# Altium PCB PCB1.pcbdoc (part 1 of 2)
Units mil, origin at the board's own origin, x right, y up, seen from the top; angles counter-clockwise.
Board outline 5175 x 2060 mil, 4 copper layers (Top Layer, Inner1, Inner2, Bottom Layer), stack 62.447 mil thick; 102 components, 59 nets, 316 pads, 177 vias.
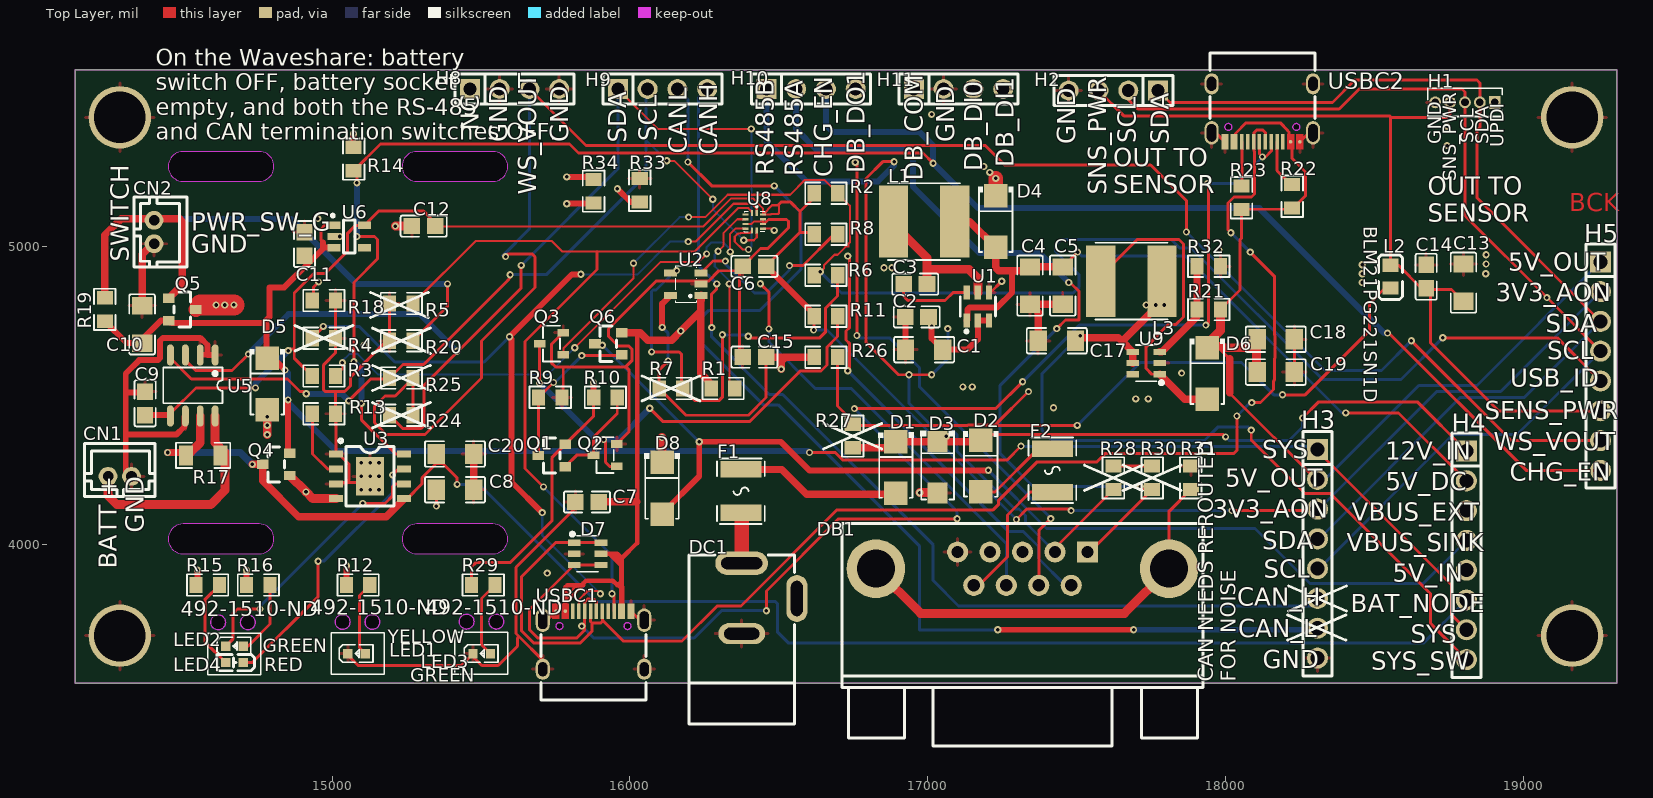
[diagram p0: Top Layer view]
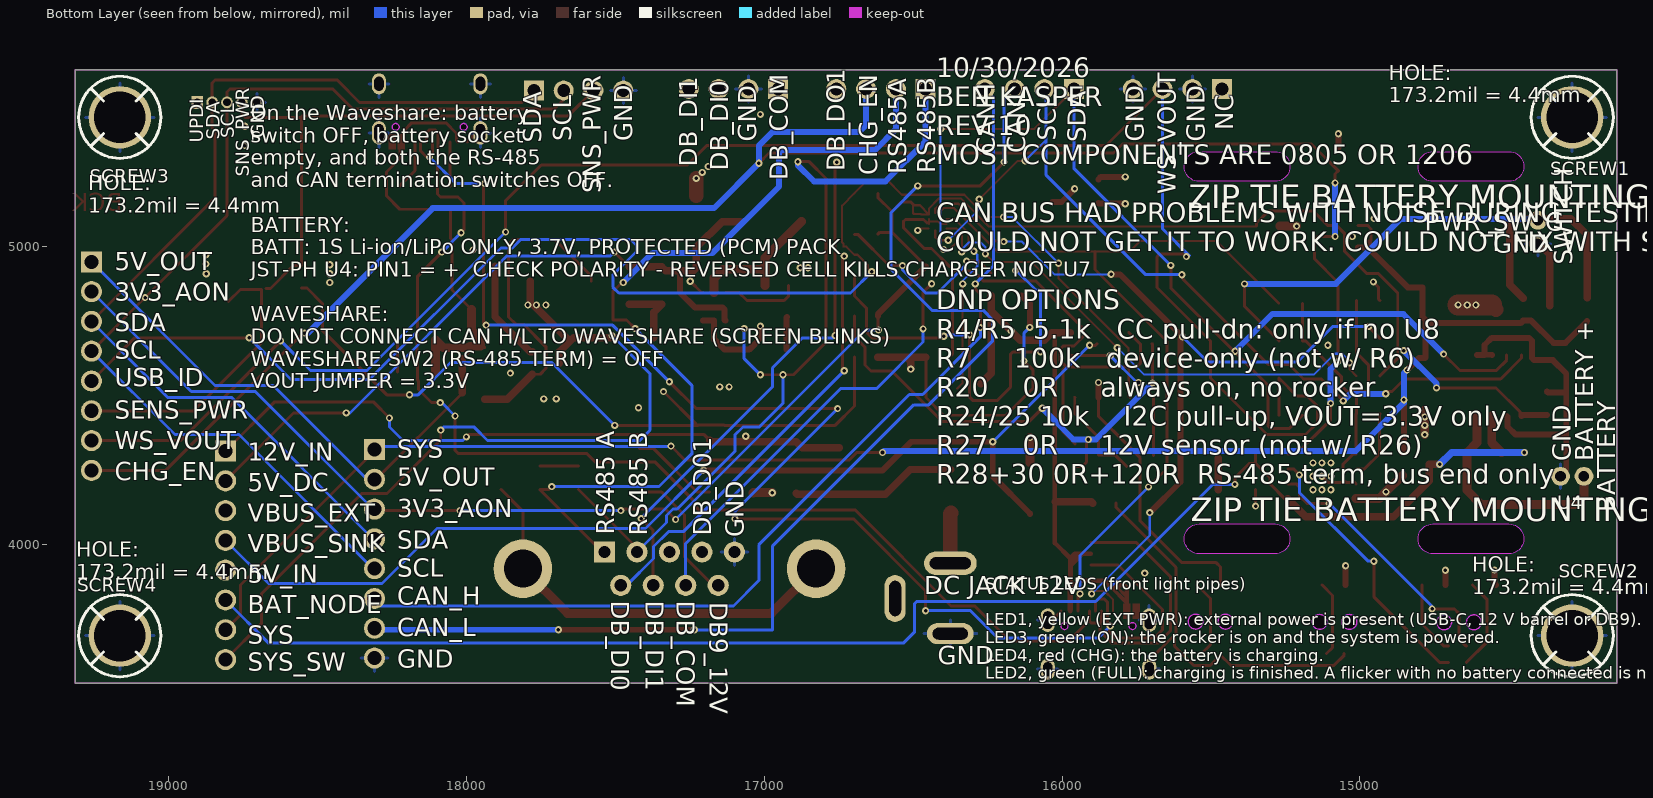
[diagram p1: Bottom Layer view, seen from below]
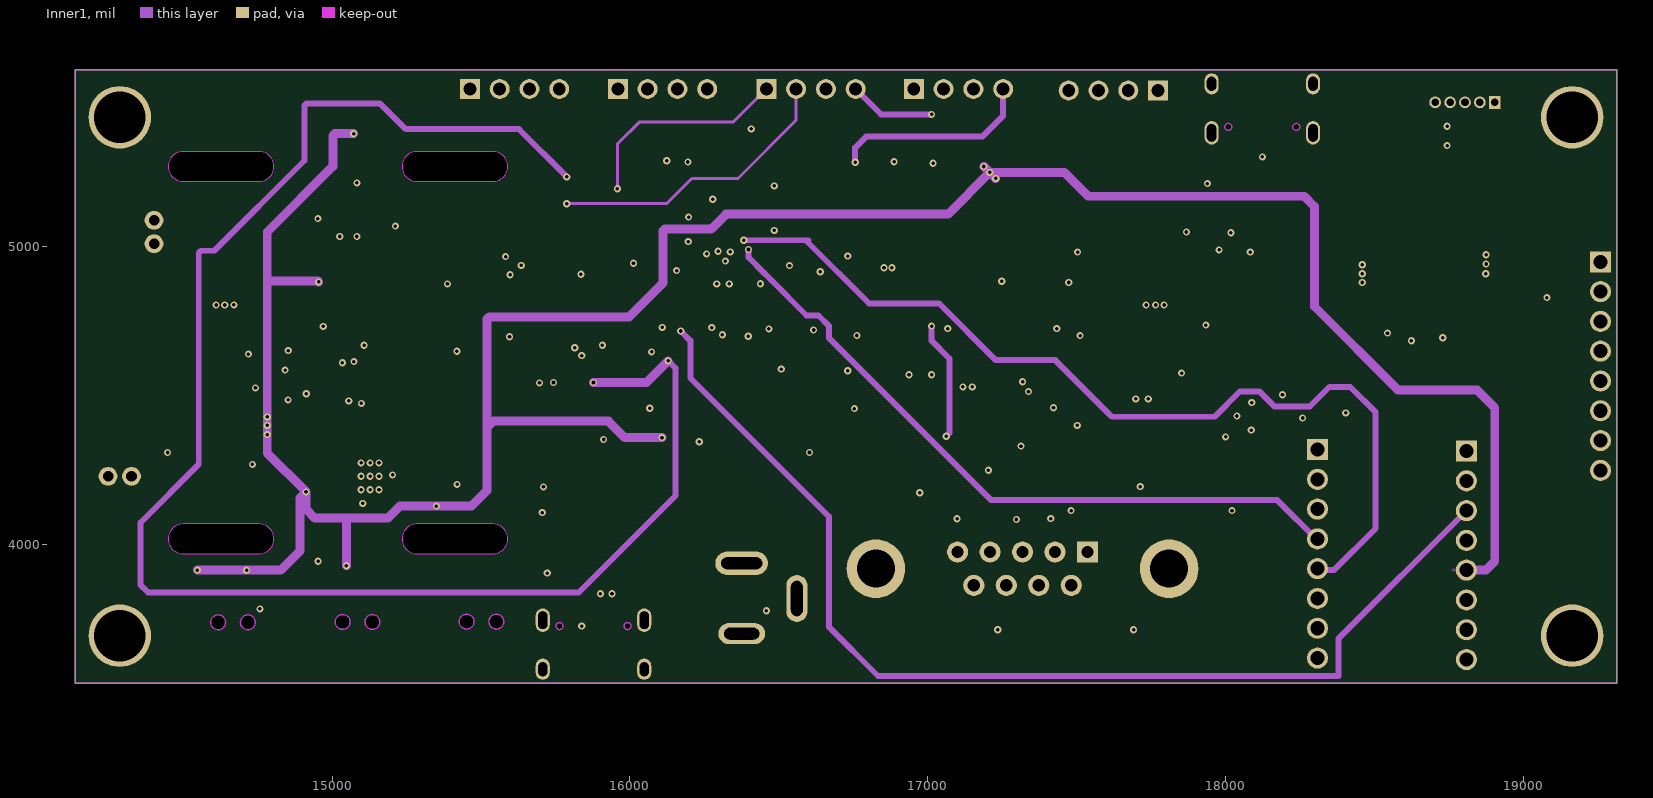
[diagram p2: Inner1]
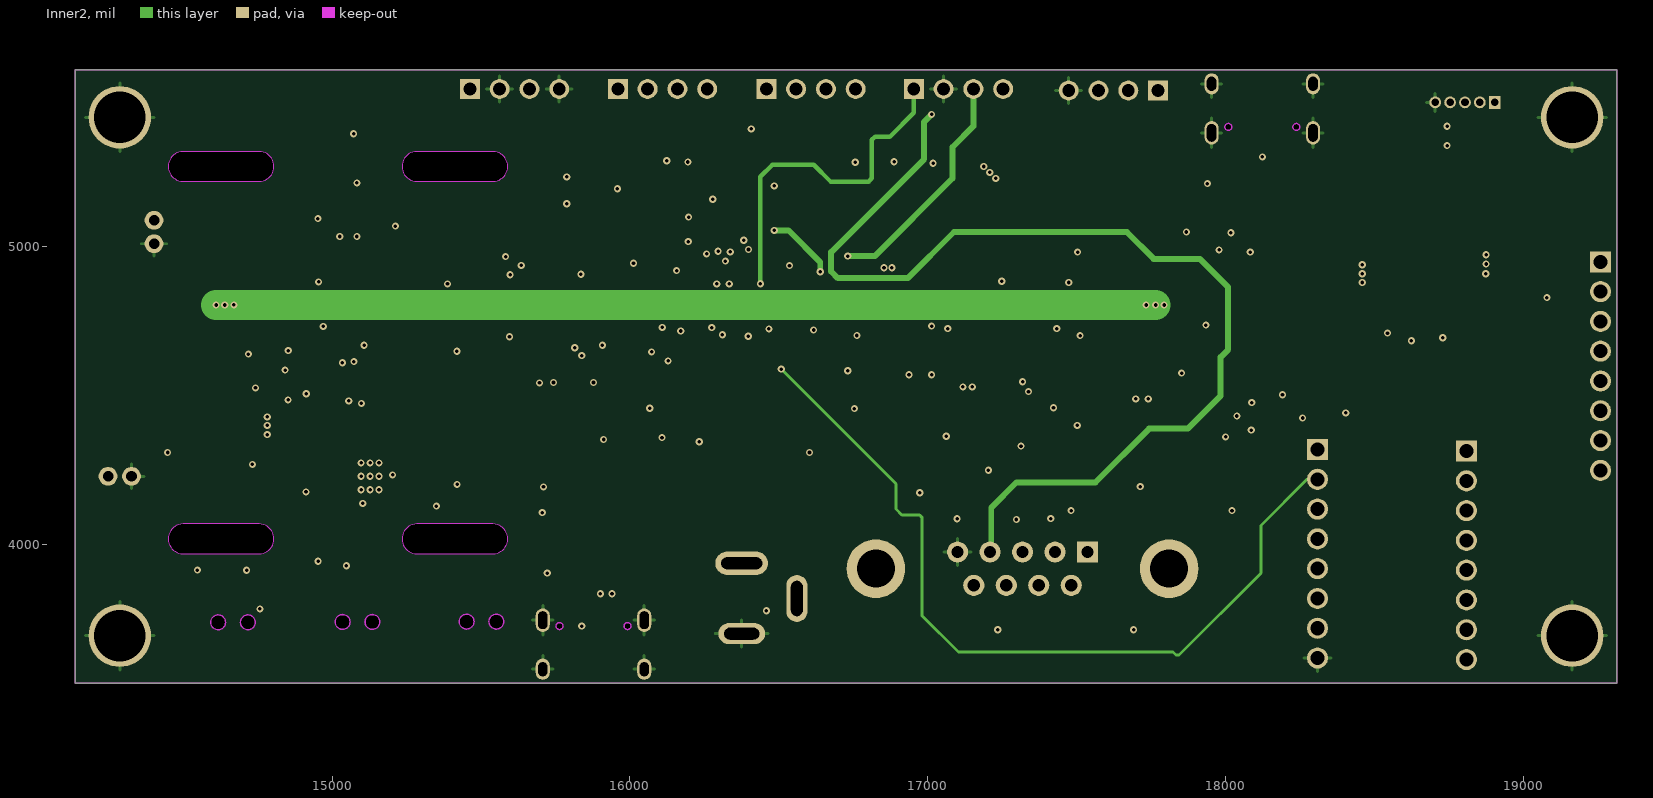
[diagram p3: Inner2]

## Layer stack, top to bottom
Top Layer: signal copper 1.378
Dielectric1: surface 8.283, 7628 RC49% 8.6mil, Dk 0
Inner1: signal copper 0.598
Dielectric2: surface 41.929, 1.1mm H/HOZ Copper, Dk 0
Inner2: signal copper 0.598
Dielectric3: surface 8.283, 7628 RC49% 8.6mil, Dk 0
Bottom Layer: signal copper 1.378

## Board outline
14137.5,5595 14137.5,3535 19312.5,3535 19312.5,5595
cut-out: 14500,5320 ccw(c14500,5270) 14450,5270 ccw(c14500,5270) 14500,5220 14755,5220 ccw(c14755,5270) 14805,5270 ccw(c14755,5270) 14755,5320
cut-out: 15285,5320 ccw(c15285,5270) 15235,5270 ccw(c15285,5270) 15285,5220 15540,5220 ccw(c15540,5270) 15590,5270 ccw(c15540,5270) 15540,5320
cut-out: 14500,4070 ccw(c14500,4020) 14450,4020 ccw(c14500,4020) 14500,3970 14755,3970 ccw(c14755,4020) 14805,4020 ccw(c14755,4020) 14755,4070
cut-out: 15285,4070 ccw(c15285,4020) 15235,4020 ccw(c15285,4020) 15285,3970 15540,3970 ccw(c15540,4020) 15590,4020 ccw(c15540,4020) 15540,4070
cut-out: 14642.5,3740 cw(c14617.5,3740) 14592.5,3740 cw(c14617.5,3740)
cut-out: 14742.5,3740 cw(c14717.5,3740) 14692.5,3740 cw(c14717.5,3740)
cut-out: 15060.5,3741.25 cw(c15035.5,3741.25) 15010.5,3741.25 cw(c15035.5,3741.25)
cut-out: 15160.5,3741.25 cw(c15135.5,3741.25) 15110.5,3741.25 cw(c15135.5,3741.25)
cut-out: 15476.5,3742.25 cw(c15451.5,3742.25) 15426.5,3742.25 cw(c15451.5,3742.25)
cut-out: 15576.5,3742.3 cw(c15551.5,3742.3) 15526.5,3742.3 cw(c15551.5,3742.3)

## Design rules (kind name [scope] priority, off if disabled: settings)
BoardOutlineClearance copperThickness1oz [All] p0: genericclearance=10 ignorepadtopadclearanceinfootprint=FALSE except(0: Arc-SplitContinuation Track-SplitContinuation SMDPad-SplitContinuation THPad-SplitContinuation Via-SplitContinuation Fill-SplitContinuation Poly-SplitContinuation Region-SplitContinuation Text-SplitContinuation)
BoardOutlineClearance copperThickness2oz [All] p0: genericclearance=10 ignorepadtopadclearanceinfootprint=FALSE except(0: Arc-SplitContinuation Track-SplitContinuation SMDPad-SplitContinuation THPad-SplitContinuation Via-SplitContinuation Fill-SplitContinuation Poly-SplitContinuation Region-SplitContinuation Text-SplitContinuation)
BoardOutlineClearance safeClearance1 [All] p0: genericclearance=10 ignorepadtopadclearanceinfootprint=FALSE except(0: Arc-SplitContinuation Track-SplitContinuation SMDPad-SplitContinuation THPad-SplitContinuation Via-SplitContinuation Fill-SplitContinuation Poly-SplitContinuation Region-SplitContinuation Text-SplitContinuation)
BoardOutlineClearance otherClearance [All] p0: genericclearance=10 ignorepadtopadclearanceinfootprint=FALSE except(0: Arc-SplitContinuation Track-SplitContinuation SMDPad-SplitContinuation THPad-SplitContinuation Via-SplitContinuation Fill-SplitContinuation Poly-SplitContinuation Region-SplitContinuation Text-SplitContinuation)
Clearance copperThickness1oz [All] p1: gap=7 ignorepadtopadclearanceinfootprint=FALSE
Clearance copperThickness2oz [All] p1: gap=7 ignorepadtopadclearanceinfootprint=FALSE
Clearance safeClearance1 [All] p1: gap=7 ignorepadtopadclearanceinfootprint=FALSE
Clearance otherClearance [All] p1: gap=7 ignorepadtopadclearanceinfootprint=FALSE
DiffPairsRouting differentialPair [All] p1: maxuncoupledlength=10 minlimit=6 maxlimit=Infinity mostfreqgap=6 toplayer_minwidth=5 toplayer_prefwidth=10 toplayer_maxwidth=100 bottomlayer_minwidth=5 bottomlayer_prefwidth=10 bottomlayer_maxwidth=100 midlayer1_minwidth=5 midlayer1_prefwidth=10 midlayer1_maxwidth=100 midlayer2_minwidth=5 midlayer2_prefwidth=10 midlayer2_maxwidth=100
PasteMaskExpansion pasteMaskExpansion [All] p1: expansion=0
PlaneConnect innerPlane [All] p1: planeconnectstyle=Relief reliefexpansion=20 reliefentries=4 reliefconductorwidth=10 reliefairgap=10
PolygonConnect copperRegion [All] p1: connectstyle=Relief reliefentries=4 reliefconductorwidth=10 polygonreliefangle="90 Angle" airgapwidth=10
RoutingVias viaSize [All] p1: viastyle="Through Hole" holewidth=12.0078 minholewidth=11.811 maxholewidth=248.0314 width=12.0078 minwidth=11.811 maxwidth=248.0314
SolderMaskExpansion solderMaskExpansion [IsVia] p1: useseparateexpansions=TRUE expansion=-1000 expansionbottom=-1000
SolderMaskExpansion solderMaskExpansion [All] p2: useseparateexpansions=TRUE expansion=2 expansionbottom=2
Width copperThickness1oz [All] p1: maxlimit=100 minlimit=5 preferedwidth=10
Width copperThickness2oz [All] p1: maxlimit=100 minlimit=8 preferedwidth=10

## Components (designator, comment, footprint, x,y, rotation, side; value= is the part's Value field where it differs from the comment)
C1 "22uF" C1206 16987.5,4655 r0 top
C2 "100nF" C0805 16962.5,4765 r0 top
C3 "100nF" C0805 16957.5,4875 r180 top
C4 "22uF" C1206 17342.5,4870 r90 top
C5 "22uF" C1206 17452.5,4870 r90 top
C6 "100nF" C0805 16417.5,4935 r0 top
C7 "1uF" C0805 15855.7,4143.7 r180 top
C8 "22uF" C1206 15412.5,4185 r180 top
C9 "100nF" C0805 14372.5,4475 r270 top
C10 "22uF" C1206 14362.5,4740 r270 top
C11 "1uF" C0805 14907.5,5010 r270 top
C12 "1uF" C0805 15307.5,5070 r0 top
C13 "22uF" C1206 18797.5,4880 r90 top
C14 "100nF" C0805 18672.5,4900 r270 top
C15 "100nF" C0805 16417.5,4630 r0 top
C17 "22uF" C1206 17432.5,4685 r180 top
C18 "22uF" C1206 18167.5,4690 r0 top
C19 "22uF" C1206 18167.5,4580 r0 top
C20 "22uF" C1206 15412.5,4305 r180 top
CN1 "B2B-PH-K-S(LF)(SN)" CONN-TH_B2B-PH-K-S 14287.5,4230 r0 top
CN2 "B2B-PH-K-S(LF)(SN)" CONN-TH_B2B-PH-K-S 14402.5,5050 r270 top
D1 "SS34" SMA_L4.3-W2.6-LS5.2-RD 16892.5,4260 r270 top
D2 "SS34" SMA_L4.3-W2.6-LS5.2-RD 17177.5,4264.23 r270 top
D3 "SMAJ18A" SMA_L4.4-W2.6-LS5.0-RD 17032.5,4260 r270 top
D4 "SS34" SMA_L4.3-W2.6-LS5.2-RD 17227.5,5085 r270 top
D5 "SS34" SMA_L4.3-W2.6-LS5.2-RD 14782.5,4540 r270 top
D6 "SS34" SMA_L4.3-W2.6-LS5.2-RD 17937.5,4575 r270 top
D7 "USBLC6-2SC6" SOT-23-6_L2.9-W1.6-P0.95-LS2.8-BL 15857.5,3970 r270 top
D8 "SS34" SMA_L4.3-W2.6-LS5.2-RD 16107.5,4190 r270 top
DB1 "A-DF 09 A/KG-T2S" DB9-TH_DB9F_C9900018961 17317.5,3920 r0 top
DC1 "PJ-002AH" DC-IN-TH_PJ-002AH 16467.5,3820 r270 top
F1 "BSMD1812-150-33V" F1812 16372.5,4180 r90 top
F2 "BSMD1812-150-33V" F1812 17417.5,4250 r90 top
H1 "GRPB051VWVN-RC" HDR-TH_5P-P1.27-V-M-1 18802.5,5485 r180 top
H2 "" HDR-TH_4P-P2.54-V-M 17622.5,5525 r180 top
H3 "" HDR-TH_8P-P2.54-V-F-1 18307.5,3970 r270 top
H4 "" HDR-TH_8P-P2.54-V-F-1 18807.5,3965 r270 top
H5 "" HDR-TH_8P-P2.54-V-F-1 19257.5,4600 r270 top
H8 "" HDR-TH_4P-P2.54-V-M 15612.5,5530 r0 top
H9 "" HDR-TH_4P-P2.54-V-M 16109.17,5530 r0 top
H10 "" HDR-TH_4P-P2.54-V-M 16607.5,5530 r0 top
H11 "" HDR-TH_4P-P2.54-V-M 17102.5,5530 r0 top
L1 "6.8uH" IND-SMD_L6.0-W6.0_SMNR6045 16987.5,5085 r180 top
L2 "BLM21PG221SN1D" L0805 18552.5,4900 r90 top
L3 "6.8uH" IND-SMD_L6.0-W6.0_SMNR6045 17682.5,4885 r0 top
LED1 "NCD0603Y2" LED0603-RD 15082.5,3635 r0 top
LED2 "KT-0603G" LED0603-RD 14672.5,3660 r0 top
LED3 "KT-0603G" LED0603-RD 15502.5,3635 r0 top
LED4 "KT-0603R" LED-SMD_L1.6-W0.8-R-RD 14672.5,3605 r180 top
Q1 "AO3401A" SOT-23_L2.9-W1.3-P1.90-LS2.4-BR 15737.5,4300 r0 top
Q2 "2N7002" SOT-23-3_L2.9-W1.3-P1.90-LS2.4-BR 15916.59,4300.97 r0 top
Q3 "2N7002" SOT-23-3_L2.9-W1.3-P1.90-LS2.4-BR 15736.59,4675 r0 top
Q4 "AO3401A" SOT-23_L2.9-W1.3-P1.90-LS2.4-BR 14812.5,4270 r0 top
Q5 "AO3401A" SOT-23_L2.9-W1.3-P1.90-LS2.4-BR 14497.5,4790 r180 top
Q6 "AO3401A" SOT-23_L2.9-W1.3-P1.90-LS2.4-BR 15927.5,4675 r0 top
R1 "910kΩ" R0805 16312.5,4525 r0 top
R2 "100kΩ" R0805 16657.5,5180 r0 top
R3 "100kΩ" R0805 14972.5,4566.67 r0 top
R4 "5.1kΩ" R0805 14972.5,4693.33 r0 top
R5 "5.1kΩ" R0805 15232.5,4810 r180 top
R6 "0Ω" R0805 16657.5,4905 r0 top
R7 "100kΩ" R0805 16137.5,4525 r0 top
R8 "10kΩ" R0805 16657.5,5042.5 r0 top
R9 "100kΩ" R0805 15732.5,4495 r0 top
R10 "100kΩ" R0805 15917.5,4495 r0 top
R11 "100kΩ" R0805 16657.5,4767.5 r0 top
R12 "1kΩ" R0805 15087.5,3865 r0 top
R13 "2kΩ" R0805 14972.5,4440 r0 top
R14 "10kΩ" R0805 15072.5,5295 r270 top
R15 "1kΩ" R0805 14582.5,3865 r0 top
R16 "1kΩ" R0805 14752.5,3865 r0 top
R17 "50mΩ" R1206 14567.5,4300 r180 top
R18 "100kΩ" R0805 14972.5,4820 r180 top
R19 "1kΩ" R0805 14237.5,4790 r90 top
R20 "0Ω" R0805 15232.5,4685 r180 top
R21 "75kΩ" R0805 17942.5,4790 r180 top
R22 "10kΩ" R0805 18222.5,5170 r90 top
R23 "10kΩ" R0805 18052.5,5165 r90 top
R24 "10kΩ" R0805 15232.5,4435 r0 top
R25 "10kΩ" R0805 15232.5,4560 r0 top
R26 "0Ω" R0805 16657.5,4630 r0 top
R27 "0Ω" R0805 16747.5,4365 r90 top
R28 "0Ω" R0805 17622.5,4225 r270 top
R29 "1kΩ" R0805 15507.5,3865 r0 top
R30 "120Ω" R0805 17752.5,4225 r90 top
R31 "0Ω" R0805 17882.5,4225 r90 top
R32 "10kΩ" R0805 17942.5,4935 r0 top
R33 "560Ω" R0805 16032.5,5190 r90 top
R34 "560Ω" R0805 15877.89,5187.1 r90 top
SCREW1 "" Screw-Hole-M4 14287.5,5434.98 r180 bottom
SCREW2 "" Screw-Hole-M4 14287.5,3695 r180 bottom
SCREW3 "" Screw-Hole-M4 19162.5,5435 r180 bottom
SCREW4 "" Screw-Hole-M4 19162.5,3695 r180 bottom
U1 "AP63205WU-7" TSOT-23-6_L2.9-W1.6-P0.95-LS2.8-BL 17167.5,4800 r0 top
U2 "TPS2041BDBVR" SOT-23-5_L3.0-W1.7-P0.95-LS2.8-BR 16187.5,4875 r0 top
U3 "TP4056-42-ESOP8" ESOP-8_L4.9-W3.9-P1.27-LS6.0-BL-EP 15127.5,4230 r270 top
U5 "INA219AIDR" SOIC-8_L4.9-W3.9-P1.27-LS6.0-BL 14532.5,4535 r180 top
U6 "AP2112K-3.3TRG1" SOT-25-5_L2.9-W1.6-P0.95-LS2.8-BL 15057.5,5035 r270 top
U8 "TUSB320LAIRWBR" X2QFN-12_L1.6-W1.6-P0.40-TL 16417.5,5085 r270 top
U9 "MT3608" SOT-23-6_L2.9-W1.6-P0.95-LS2.8-BL 17732.5,4610 r90 top
USBC1 "TYPE-C-31-M-12" USB-C_SMD-TYPE-C-31-M-12_1 15877.5,3680 r0 top
USBC2 "TYPE-C-31-M-12" USB-C_SMD-TYPE-C-31-M-12_1 18122.5,5450 r180 top

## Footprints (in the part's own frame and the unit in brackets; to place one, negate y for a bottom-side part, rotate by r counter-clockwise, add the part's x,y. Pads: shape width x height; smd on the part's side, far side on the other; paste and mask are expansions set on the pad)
C0805 [mm]
  rect 1.41x1.35 smd paste-100 mask+0.051: 1(-1,0) 2(1,0)
  silkscreen extent -1.96,-0.9 1.96,0.9
C1206 [mm]
  rect 1.485x1.728 smd paste-100 mask+0.051: 1(-1.593,0) 2(1.593,0)
  silkscreen extent -2.56,-1.09 2.56,1.09
CONN-TH_B2B-PH-K-S [mm]
  round 1.6 hole 0.9: 1(1,0) 2(-1,0)
  silkscreen extent -3,-1.7 3,2.8
DB9-TH_DB9F_C9900018961 [mm]
  rect 1.8x1.8 hole 1.05 paste+0 mask+0.05: 1(5.54,1.42)
  round 1.8 hole 1.05 paste+0 mask+0.05: 2(2.77,1.42) 3(0,1.42) 4(-2.77,1.42) 5(-5.54,1.42) 6(4.155,-1.42) 7(1.385,-1.42) 8(-1.385,-1.42) 9(-4.155,-1.42)
  round 5 hole 3.25 paste+0 mask+0.05: 10(-12.5,0) 11(12.5,0)
  silkscreen extent -15.4,-15.13 15.4,3.87
DC-IN-TH_PJ-002AH [mm]
  oval 2x4.5 hole 1 slot 3.5 at 90 deg copper offset 0.001,0: 1(-3.001,-2.35)
  oval 1.8x4 hole 1 slot 3 at 90 deg copper offset 0,0: 2(3,-2.35)
  oval 4x1.8 hole 1 slot 3 at 0 deg copper offset 0,0.001: 3(0,2.349)
  silkscreen extent -3.7,-6.85 10.7,2.15
ESOP-8_L4.9-W3.9-P1.27-LS6.0-BL-EP [mm]
  rect 0.6x1.2 smd: 1(-1.905,-2.908) 2(-0.635,-2.908) 3(0.635,-2.908) 4(1.905,-2.908) 5(1.905,2.908) 6(0.635,2.908) 7(-0.635,2.908) 8(-1.905,2.908)
  rect 3.3x2.4 smd: 9(0,0)
  silkscreen extent -3.2,-2.67 2.55,2.05
F1812 [mil]
  rect 55.38x137.76 smd paste-3937.01 mask+2: 1(-72.97,0) 2(72.97,0)
  silkscreen extent -110,-80 110,80
HDR-TH_4P-P2.54-V-M [mm]
  rect 1.7x1.7 hole 1.1: 1(-3.81,0)
  round 1.7 hole 1.1: 2(-1.27,0) 3(1.27,0) 4(3.81,0)
  silkscreen extent -5.08,-1.27 5.08,1.27
HDR-TH_5P-P1.27-V-M-1 [mm]
  rect 1x1.1 hole 0.65: 1(-2.54,0)
  round 1 hole 0.65: 2(-1.27,0) 3(0,0) 4(1.27,0) 5(2.54,0)
  silkscreen extent -3.17,-1.2 3.17,1.2
HDR-TH_8P-P2.54-V-F-1 [mm]
  rect 1.8x1.8 hole 1.2: 1(-8.89,0)
  round 1.8 hole 1.2: 2(-6.35,0) 3(-3.81,0) 4(-1.27,0) 5(1.27,0) 6(3.81,0) 7(6.35,0) 8(8.89,0)
  silkscreen extent -10.41,-1.25 10.41,1.25
IND-SMD_L6.0-W6.0_SMNR6045 [mm]
  rect 2.474x6.12 smd: 1(2.603,0) 2(-2.603,0)
  silkscreen extent -3.08,-3.28 3.08,3.28
L0805 [mil]
  rect 44.59x54.21 smd paste-3937.01 mask+2: 1(-38.04,0) 2(38.04,0)
  silkscreen extent -77,-40 73,40
LED0603-RD [mm]
  rect 0.8x0.8 smd: 1(-0.749,0) 2(0.749,0)
  silkscreen extent -1.49,-0.75 1.39,0.76
LED-SMD_L1.6-W0.8-R-RD [mm]
  rect 0.8x0.8 smd: 1(0.75,0) 2(-0.75,0)
  silkscreen extent -1.7,-0.7 1.47,0.7
R0805 [mm]
  rect 1.133x1.377 smd paste-100 mask+0.051: 1(-1,0) 2(1,0)
  silkscreen extent -1.76,-0.92 1.76,0.92
R1206 [mil]
  rect 47.54x66.97 smd paste-3937.01 mask+2: 1(-58.22,0) 2(58.22,0)
  silkscreen extent -91,-42 91,42
Screw-Hole-M4 [mil]
  round 210 hole 173.2: 1(0,0)
  silkscreen extent -138,-138 138,138
SMA_L4.3-W2.6-LS5.2-RD [mm]
  rect 2x2 smd: 1(-2.2,0) 2(2.2,0)
  silkscreen extent -2.98,-1.5 2.6,1.5
SMA_L4.4-W2.6-LS5.0-RD [mm]
  rect 1.8x1.7 smd paste+0 mask+0.051: 1(-2.192,0) 2(2.192,0)
  silkscreen extent -3.11,-1.48 2.73,1.48
SOIC-8_L4.9-W3.9-P1.27-LS6.0-BL [mm]
  oval 0.588x1.8 smd paste+0 mask+0.051: 1(-1.905,-2.6) 2(-0.635,-2.6) 3(0.635,-2.6) 4(1.905,-2.6) 5(1.905,2.6) 6(0.635,2.6) 7(-0.635,2.6) 8(-1.905,2.6)
  silkscreen extent -2.53,-1.52 2.53,1.52
SOT-23-3_L2.9-W1.3-P1.90-LS2.4-BR [mm]
  rect 1x0.65 smd: 1(1,-0.95) 2(1,0.95) 3(-1,0)
  silkscreen extent -0.73,-1.53 0.73,1.53
SOT-23-5_L3.0-W1.7-P0.95-LS2.8-BR [mm]
  rect 1.1x0.6 smd: 1(1.3,-0.95) 2(1.3,0) 3(1.3,0.95) 4(-1.3,0.95) 5(-1.3,-0.95)
  silkscreen extent -0.9,-1.55 0.9,1.55
SOT-23-6_L2.9-W1.6-P0.95-LS2.8-BL [mil]
  rect 20.95x42.2 smd: 1(-37.4,-45.24) 2(0,-45.24) 3(37.4,-45.24) 4(37.4,45.24) 5(0,45.24) 6(-37.4,45.24)
  silkscreen extent -72,-57 61,35
SOT-23_L2.9-W1.3-P1.90-LS2.4-BR [mm]
  rect 1x0.8 smd: 1(1.15,-0.95) 2(1.15,0.95) 3(-1.15,0)
  silkscreen extent -0.7,-1.5 0.7,1.5
SOT-25-5_L2.9-W1.6-P0.95-LS2.8-BL [mil]
  rect 24.5x43.5 smd: 1(-37.39,-51.18) 2(-0.02,-51.18) 3(37.39,-51.18) 4(37.39,51.18) 5(-37.39,51.18)
  silkscreen extent -75,-60 56,20
TSOT-23-6_L2.9-W1.6-P0.95-LS2.8-BL [mm]
  rect 0.55x1.2 smd: 1(-0.95,-1.2) 2(0,-1.2) 3(0.95,-1.2) 4(0.95,1.2) 5(0,1.2) 6(-0.95,1.2)
  silkscreen extent -1.5,-2.25 1.5,0.8
USB-C_SMD-TYPE-C-31-M-12_1 [mm]
  oval 1.2x2 hole 0.8 slot 1.5 at 90 deg paste+0 mask+0.051: 1(4.325,1.706) 4(-4.325,1.706)
  oval 1.2x1.8 hole 0.8 slot 1.2 at 90 deg copper offset 0,0 paste+0 mask+0.051: 2(4.325,-2.474) 3(-4.325,-2.474)
  round 0.3 smd: A1B12(-3.2,2.474) A4B9(-2.4,2.474)
  rect 0.3x1.3 smd paste-100 mask+0.051: A5(-1.25,2.474) A6(-0.25,2.474) A7(0.25,2.474) A8(1.25,2.474) B5(1.75,2.474) B6(0.75,2.474) B7(-0.75,2.474) B8(-1.75,2.474)
  rect 0.6x1.3 smd paste-100 mask+0.051: B1A12(3.2,2.474) B4A9(2.4,2.474)
  Top Layer region: -2.9,1.824 -2.9,3.124 -3.2,3.124 -3.2,3.124 -3.5,3.124 -3.5,1.824 -3.2,1.824 -3.2,1.824
  Top Layer region: -2.1,1.824 -2.1,3.124 -2.4,3.124 -2.4,3.124 -2.7,3.124 -2.7,1.824 -2.4,1.824 -2.4,1.824
  Board Outline Layer circle w0.003: c-2.9,1.206 r0.3
  Board Outline Layer circle w0.003: c2.9,1.206 r0.3
  Board Outline Layer region: -2.6,1.206 -2.63,1.075 -2.713,0.971 -2.833,0.913 -2.967,0.913 -3.087,0.971 -3.17,1.075 -3.2,1.206 -3.2,1.206 -3.17,1.336 -3.087,1.44 -2.967,1.498 -2.833,1.498 -2.713,1.44 -2.63,1.336 -2.6,1.206
  Board Outline Layer region: -2.6,1.206 -2.609,1.134 -2.634,1.066 -2.675,1.007 -2.729,0.959 -2.794,0.925 -2.864,0.908 -2.936,0.908 -3.006,0.925 -3.07,0.959 -3.124,1.007 -3.166,1.066 -3.191,1.134 -3.2,1.206 -3.191,1.277 -3.166,1.345 -3.124,1.405 -3.07,1.453 -3.006,1.486 -2.936,1.503 -2.864,1.503 -2.794,1.486 -2.729,1.453 -2.675,1.405 -2.634,1.345 -2.609,1.277
  Board Outline Layer region: 3.2,1.206 3.17,1.075 3.087,0.971 2.967,0.913 2.833,0.913 2.713,0.971 2.63,1.075 2.6,1.206 2.6,1.206 2.63,1.336 2.713,1.44 2.833,1.498 2.967,1.498 3.087,1.44 3.17,1.336 3.2,1.206
  Board Outline Layer region: 3.2,1.206 3.191,1.134 3.166,1.066 3.124,1.007 3.07,0.959 3.006,0.925 2.936,0.908 2.864,0.908 2.794,0.925 2.729,0.959 2.675,1.007 2.634,1.066 2.609,1.134 2.6,1.206 2.609,1.277 2.634,1.345 2.675,1.405 2.729,1.453 2.794,1.486 2.864,1.503 2.936,1.503 3.006,1.486 3.07,1.453 3.124,1.405 3.166,1.345 3.191,1.277
  Multi-Layer board cut-out: -2.6,1.206 -2.63,1.075 -2.713,0.971 -2.833,0.913 -2.967,0.913 -3.087,0.971 -3.17,1.075 -3.2,1.206 -3.2,1.206 -3.17,1.336 -3.087,1.44 -2.967,1.498 -2.833,1.498 -2.713,1.44 -2.63,1.336 -2.6,1.206
  Multi-Layer board cut-out: 3.2,1.206 3.17,1.075 3.087,0.971 2.967,0.913 2.833,0.913 2.713,0.971 2.63,1.075 2.6,1.206 2.6,1.206 2.63,1.336 2.713,1.44 2.833,1.498 2.967,1.498 3.087,1.44 3.17,1.336 3.2,1.206
  silkscreen extent -4.47,-5.09 4.47,0.49
X2QFN-12_L1.6-W1.6-P0.40-TL [mm]
  rect 0.505x0.2 smd: 1(-0.75,0.2) 2(-0.75,-0.2) 7(0.75,-0.2) 8(0.75,0.2)
  rect 0.2x0.505 smd: 3(-0.6,-0.75) 4(-0.2,-0.75) 5(0.2,-0.75) 6(0.6,-0.75) 9(0.6,0.75) 10(0.2,0.75) 11(-0.2,0.75) 12(-0.6,0.75)
  silkscreen extent -1.35,-0.87 0.86,0.87

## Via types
v1: diameter 24.02, hole 12, Top Layer to Bottom Layer, 177 vias

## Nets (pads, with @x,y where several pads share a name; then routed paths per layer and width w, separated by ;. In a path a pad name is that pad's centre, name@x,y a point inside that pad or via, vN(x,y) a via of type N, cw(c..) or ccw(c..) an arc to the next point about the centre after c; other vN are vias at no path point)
3V3_AON: C6.2 C9.2 C12.2 H3.3 H5.2 R2.1 R3.1 R8.1 R11.1 U5.5 U6.5 U8.12 | length 6842.2
  Top Layer w7.09: C12.2@15346.87,5070 15348.25,5068.62 16246.12,5068.62 16340.41,5162.91 16412.74,5162.91 16447.03,5128.62 U8.12@16447.03,5108.62 ; 16500.23,5113.88 16496.99,5110.64 16474.42,5110.64 16472.4,5108.62 16462.03,5108.62 U8.12@16447.03,5108.62 ; 16500.59,5114.24 16500.59,5136.28 16496.87,5140 16476.87,5140 U8.12@16447.03,5108.62
  Top Layer w10: U5.5@14457.5,4432.63 14463.13,4438.27 14463.13,4446.84 14543.13,4526.84 v1(14743.13,4526.84) ; v1(14853.13,4651.84) 14858.13,4656.84 14873.13,4656.84 ; R3.1@14933.13,4566.67 14873.13,4626.67 14873.13,4656.84 ; C12.2@15346.87,5070 15346.87,5080.63 15307.5,5120 15156.29,5120 U6.5@15108.68,5072.39 15078.68,5072.39 15052.5,5046.21 15052.5,4986.21 14976.29,4910 14937.5,4910 14873.13,4845.63 14873.13,4656.84 ; C6.2@16456.87,4935 16571.01,5049.14 ; 16496.87,5140 16506.87,5150 16539.52,5150 16571.01,5118.51 ; v1(16616.18,4721.01) 16618.13,4722.95 R11.1@16618.13,4767.5 ; R8.1@16618.13,5042.5 16611.49,5049.14 16571.01,5049.14 ; R2.1@16618.13,5180 16618.13,5165.63 16571.01,5118.51 ; v1(17296.94,4084.99) 17331.96,4120 17475.63,4120 v1(17480.63,4115) ; v1(18020.63,4115) H3.3@18307.5,4115 ; 16571.01,5049.14 16571.01,5118.51
  Top Layer w20: C9.2@14372.5,4435.63 14454.51,4435.63 U5.5@14457.5,4432.63 ; C6.2@16456.87,4935 16618.13,4773.74 R11.1@16618.13,4767.5
  Bottom Layer w10: v1(16616.18,4721.01) 16660.92,4721.01 v1(17296.94,4084.99) ; v1(17480.63,4115) v1(18020.63,4115) ; H3.3@18307.5,4115 18707.5,4515 18922.5,4515 H5.2@19257.5,4850
  Bottom Layer w20: v1(14743.13,4526.84) 14743.13,4541.84 v1(14853.13,4651.84)
5V_DC: C4.2 C5.2 D4.2 H4.2 L1.2 U1.1 | length 2468.8
  Top Layer w10: C5.2@17452.5,4932.7 v1(17502.5,4982.7) ; v1(18402.5,4442.7) 18579.79,4442.7 H4.2@18807.5,4215
  Top Layer w20: U1.1@17130.1,4752.76 17132.5,4755.16 17132.5,4790 17139.57,4797.07 17232.5,4797.07 17282.5,4847.07 17282.5,4909.53 17292.97,4920
  Top Layer w25: L1.2@17079.98,5085 17140.89,5085 D4.2@17227.5,4998.39 17227.5,4930 ; 17227.5,4929.53 17237.03,4920 17292.97,4920 17329.8,4920 C4.2@17342.5,4932.7 C5.2@17452.5,4932.7
  Bottom Layer w10: v1(17502.5,4982.7) 17515.2,4970 17862.5,4970 18389.8,4442.7 v1(18402.5,4442.7)
5V_IN: C8.2 D4.1 D5.2 D8.1 H4.5 Q4.1 R12.1 R14.1 R15.1 R16.1 R18.2 U3.4 | length 9878.7
  Top Layer w10: R18.2@14933.13,4820 14937.5,4824.37 14937.5,4865 v1(14955,4882.5) ; C8.2@15349.8,4185 15350.16,4184.64 v1(15350.16,4130)
  Top Layer w20: R15.1@14543.13,3865 14548.13,3870 v1(14548.13,3915.04) ; R16.1@14713.13,3865 v1(14713.13,3915) ; R12.1@15048.13,3865 v1(15048.13,3930) ; R14.1@15072.5,5334.37 v1(15072.5,5380)
  Top Layer w30: v1(14782.5,4370) v1(14782.5,4400.76) v1(14782.5,4429.31) D5.2@14782.5,4453.39 ; Q4.1@14857.77,4232.6 v1(14912.64,4177.74) 14935.38,4155 U3.4@15013,4155 ; D8.1@16107.5,4276.61 v1(16107.5,4360)
  Top Layer w50: D4.1@17227.5,5171.61 v1(17227.5,5230)
  Inner1 w30: v1@14548.17,3915 v1(14713.13,3915) 14827.5,3915 14892.5,3980 14892.5,4157.6 v1(14912.64,4177.74) ; v1(14955,4882.5) 14952.34,4885.16 14782.5,4885.16 ; v1(15048.13,3930) 15048.13,4085.99 15052.14,4090 ; v1(15072.5,5380) 15009.57,5380 15002.5,5372.93 15002.5,5270 14782.5,5050 14782.5,4885.16 ; v1(16107.5,4360) 15982.5,4360 15927.5,4415 15541.5,4415 15520.43,4393.93 ; v1(17187.5,5270) v1(17207.5,5250) ; v1(17227.5,5230) v1(17207.5,5250) ; H4.5@18807.5,3915 18872.5,3915 18902.5,3945 18902.5,4460 18842.5,4520 18577.5,4520 18297.5,4800 18297.5,5135 18262.5,5170 17537.5,5170 17457.5,5250 v1(17207.5,5250) ; 14782.5,4885.16 v1(14782.5,4429.31) v1(14782.5,4400.76) v1(14782.5,4370) 14782.5,4307.88 v1(14912.64,4177.74) ; v1(14912.64,4177.74) 14912.64,4119.86 14942.5,4090 15052.14,4090 ; 15052.14,4090 15187.5,4090 15227.5,4130 v1(15350.16,4130) 15467.5,4130 15520.43,4182.93 15520.43,4393.93 ; 15520.43,4393.93 15520.43,4757.93 15527.5,4765 15997.5,4765 16110.43,4877.93 16110.43,5052.93 16117.5,5060 16272.5,5060 16322.5,5110 17067.5,5110 v1(17207.5,5250)
5V_OUT: C15.2 C18.1 C19.1 D6.1 H3.2 H5.1 Q1.2 R7.1 R10.1 R21.1 R22.1 R23.1 R26.1 R29.1 R34.2 U2.5 USBC2.A4B9 USBC2.B4A9 | length 13837.6
  Top Layer w10: R29.1@15468.13,3865 15468.13,3925.63 15482.5,3940 15597.5,3940 15737.5,4080 15737.5,4292.12 Q1.2@15782.77,4337.4 15878.13,4432.76 R10.1@15878.13,4495 ; v1(16128.13,4617.48) 16098.13,4587.48 R7.1@16098.13,4525 16188.13,4435 16397.5,4435 16456.87,4494.37 C15.2@16456.87,4630 ; R21.1@17981.87,4790 18047.5,4855.63 18047.5,5023.82 18052.5,5028.82 18052.5,5126.41 18222.5,5126.41 18267.5,5171.41 18267.5,5251.41 18222.5,5296.41 18222.5,5346.41 ; 18012.5,4510 H3.2@18307.5,4215 ; 18012.5,4625 D6.1@17975.89,4661.61 ; USBC2.B4A9@18028.01,5352.59 18032.5,5357.09 18032.5,5381 18067.91,5416.41 18182.5,5416.41 18207.06,5391.85 18207.06,5390.27 18211.5,5385.83 18211.5,5357.41 18222.5,5346.41 ; C19.1@18103.08,4581.72 C19.1@18104.8,4580 ; USBC2.A4B9@18216.99,5352.6 18222.5,5347.09 18222.5,5346.41 ; D6.1@17975.89,4661.61 D6.1@17937.5,4661.61 D6.1@17975.89,4661.61
  Top Layer w20: v1(15787.5,5235) 15869.35,5235 R34.2@15877.89,5226.47 ; v1(15877.5,4545) 15877.5,4495.63 R10.1@15878.13,4495 ; v1(16108.13,4730) 16108.13,4809.41 U2.5@16136.32,4837.6
  Top Layer w25: C15.2@16456.87,4630 16521.7,4630 ; v1(16507.5,4590) 16507.5,4615.8 16521.7,4630 ; R26.1@16618.13,4630 16521.7,4630 ; 18012.5,4510 18012.5,4625
  Top Layer w30: R21.1@17981.87,4790 17981.87,4719.37 17952.5,4690 17952.5,4666.61 17987.5,4666.61 17992.5,4661.61 18076.41,4661.61 18103.08,4688.28 C19.1@18103.08,4581.72
  Inner1 w20: v1(15787.5,5235) 15627.5,5395 15247.5,5395 15160.43,5482.07 14914.57,5482.07 14907.5,5475 14907.5,5290 14604.57,4987.07 14559.57,4987.07 14552.5,4980 14552.5,4270 14357.5,4075 14357.5,3865 14382.5,3840 15827.5,3840 16152.5,4165 16152.5,4593.11 v1(16128.13,4617.48)
  Inner1 w30: v1(15877.5,4545) 16055.65,4545 v1(16128.13,4617.48)
  Inner2 w10: v1(16507.5,4590) 16892.5,4205 16892.5,4120 16912.5,4100 16972.5,4100 16979.57,4092.93 16979.57,3762.93 17102.5,3640 17822.5,3640 17832.5,3630 17842.5,3630 18117.5,3905 18117.5,4065 18272.5,4220 H3.2@18307.5,4220
  Bottom Layer w10: v1(16108.13,4730) 16128.13,4710 v1(16128.13,4617.48) ; H3.2@18307.5,4215 18327.5,4215 18647.5,4535 18842.5,4535 H5.1@19257.5,4950
12V_IN: C1.2 C2.2 D1.1 D2.1 D3.1 H4.1 R27.1 U1.2 U1.3 | length 2952.4
  Top Layer w10: D2.1@17182.5,4350.84 17202.5,4370.84 17990.75,4370.84 v1(17999.09,4362.49) ; v1(18257.5,4425.84) 18311.66,4480 18642.5,4480 H4.1@18807.5,4315
  Top Layer w20: v1(17012.5,4733.99) 17012.5,4692.7 C1.2@17050.2,4655 17132.5,4655 17167.5,4690 U1.2@17167.5,4752.76 U1.3@17204.9,4752.76
  Top Layer w25: R27.1@16747.5,4325.63 16871.52,4325.63 D1.1@16892.5,4346.61 16892.79,4346.32 D3.1@17032.5,4346.32 17177.98,4346.32 D2.1@17182.5,4350.84
  Inner1 w20: v1(17012.5,4733.99) 17012.5,4685 17072.5,4625 17072.5,4375.31 v1(17061.58,4364.39)
  Bottom Layer w10: v1(17999.09,4362.49) 18010.97,4350.61 18212.28,4350.61 18257.5,4395.84 v1(18257.5,4425.84)
$1N323: C3.2 U1.6 | length 264.8
  Top Layer w10: C3.2@16918.13,4870 16918.13,4834.37 16932.5,4820 17057.5,4820 17084.74,4847.24 U1.6@17130.1,4847.24
BAT_NODE: C20.2 H4.6 Q4.3 R17.2 U3.5 U5.7 | length 5188.8
  Top Layer w10: U3.5@15242,4155 15252,4155 15302,4205 15302,4225 C20.2@15349.8,4272.8 ; C20.2@15349.8,4305 C20.2@15349.8,4272.8 ; v1(15419.8,4202.8) 15419.8,4224.68 15371.68,4272.8 C20.2@15349.8,4272.8
  Top Layer w25: v1(14448.15,4310) R17.2@14524.28,4310 ; v1(14732.5,4270) Q4.3@14767.23,4270 14767.23,4215.27 14887.5,4095 15182,4095 U3.5@15242,4155
  Top Layer w30: R17.2@14524.28,4310 14557.5,4343.22 U5.7@14557.5,4432.63
  Bottom Layer w10: v1(15419.8,4202.8) 15494.2,4202.8 15887,3810 16487.5,3810 16494.57,3802.93 16494.57,3707.93 16532.5,3670 18662.5,3670 H4.6@18807.5,3815
  Bottom Layer w25: v1(14448.15,4310) 14692.5,4310 v1(14732.5,4270)
BATT_P: CN1.2 R17.1 U5.8 | length 743.2
  Top Layer w30: CN1.2@14248.13,4220 14248.13,4165 14278.13,4135 14592.5,4135 14640.72,4183.22 14640.72,4310 14607.5,4343.22 U5.8@14607.5,4432.63
BOOST_FB: R21.2 R32.1 U9.3 | length 343.7
  Top Layer w25: U9.3@17777.74,4647.4 17784.9,4647.4 17903.13,4765.63 R21.2@17903.13,4790 R32.1@17903.13,4935
BOOST_SW: D6.2 L3.2 U9.1 | length 1084.4
  Top Layer w10: L3.2@17580.02,4885 17580.02,4902.52 17702.5,5025 17842.5,5025 17857.5,5010 17857.5,4765 17832.5,4740 17807.5,4740 17732.5,4665 17732.5,4591.74 17751.64,4572.6 U9.1@17777.74,4572.6
  Top Layer w25: U9.1@17777.74,4572.6 17861.95,4488.39 D6.2@17937.5,4488.39
BUCK_SW: C3.1 L1.1 U1.5 | length 498.7
  Top Layer w30: L1.1@16875.02,5085 16996.87,4963.15 16996.87,4930.79 ; C3.1@16996.87,4870 16996.87,4930.79 ; U1.5@17167.5,4847.24 17167.5,4895 17137.5,4925 17002.66,4925 16996.87,4930.79
CANH: H3.6 H9.4 | length 3362.7
  Top Layer w10: v1(16274.17,4728.99) 16274.17,4841.67 16290.94,4858.44 v1(16290.94,4876.01)
  Bottom Layer w10: H9.4@16259.17,5530 16229.17,5500 16229.17,4937.78 v1(16290.94,4876.01) ; v1(16274.17,4728.99) 16274.17,4698.33 16467.5,4505 16512.5,4505 17017.5,4000 17017.5,3880 17102.5,3795 18287.5,3795 H3.6@18307.5,3815
CANL: H3.7 H9.3 | length 4022.8
  Top Layer w10: v1(16194.17,5285) 16274.17,5205 v1(16484.17,5205)
  Top Layer w20: v1(17234.17,3715) v1(17690.5,3715)
  Bottom Layer w10: H9.3@16159.17,5530 16194.17,5495 v1(16194.17,5285) ; v1(16484.17,5205) 16574.17,5115 16574.17,4925 16436.24,4787.07 16264.57,4787.07 16232.5,4755 16232.5,4685 16447.5,4470 16497.5,4470 16972.5,3995 16972.5,3715 v1(17234.17,3715)
  Bottom Layer w20: v1(17690.5,3715) H3.7@18307.5,3715
CC1: R4.1 U8.1 USBC1.A5 | length 2915.9
  Top Layer w7.09: USBC1.A5@15828.29,3777.41 15828.29,3815.79 15857.5,3845 15891.65,3845 v1(15900.64,3836.01) ; v1(16195.37,5018.02) 16220.52,5018.02 16347.5,5145 16408.39,5145 16425.37,5128.02 U8.1@16425.37,5114.53
  Top Layer w10: R4.1@14933.13,4693.33 14970.69,4730.89 v1(14970.69,4733.33)
  Top Layer w20: v1(15705.37,4108.02) 15602.5,4210.89 15602.5,4691.52 v1(15595.69,4698.33) 15805.37,4908.02 v1(15835.37,4908.02)
  Bottom Layer w7.09: v1(15705.37,4108.02) 15705.37,4031.28 v1(15900.64,3836.01) ; v1(15835.37,4908.02) 16025.52,4908.02 16135.52,5018.02 v1(16195.37,5018.02)
  Bottom Layer w10: v1(14970.69,4733.33) 15090.69,4733.33 15210.69,4613.33 15510.69,4613.33 v1(15595.69,4698.33)
CC2: R5.1 U8.2 USBC1.B5 | length 2739.3
  Top Layer w7.09: R5.1@15271.87,4810 15481.87,5020 15737.5,5020 15772.97,4984.53 15889.63,4984.53 16217.03,4984.53 16362.5,5130 16397.5,5130 16408.46,5119.04 16408.46,5115.71 U8.2@16409.63,5114.53
  Top Layer w10: v1(15709.63,4194.53) 15647.5,4256.66 15647.5,4682.4 15889.63,4924.53 15889.63,4984.53 ; v1(15939.63,3836.01) 15946.4,3829.24 USBC1.B5@15946.4,3777.41
  Bottom Layer w10: v1(15709.63,4194.53) 15939.63,3964.53 v1(15939.63,3836.01)
CHG_EN: H5.8 H10.3 R14.2 U3.8 | length 6382.3
  Top Layer w10: v1(15073.38,4615) 15073.38,4880.88 15152.5,4960 15152.5,5025 15142.5,5035 v1(15083.38,5035) ; v1(15083.38,5215) 15083.38,5244.75 R14.2@15072.5,5255.63 15162.5,5345.63 15796.87,5345.63 15827.5,5315 16983.12,5315 v1(17017.49,5280.63) ; v1(15098.38,4475) 15098.38,4420 15213.38,4305 U3.8@15242,4305 ; v1(18542.49,4710.63) 18547.49,4710.63 19008.12,4250 H5.8@19257.5,4250
  Bottom Layer w20: v1(15073.38,4615) 15098.38,4590 v1(15098.38,4475) ; v1(15083.38,5035) v1(15083.38,5215) ; H10.3@16657.5,5530 16657.5,5410 16682.5,5385 16972.5,5385 17017.49,5340.01 v1(17017.49,5280.63) 17168.12,5130 18112.5,5130 18531.87,4710.63 v1(18542.49,4710.63)
CHRG_N: LED4.2 U3.7 | length 913.6
  Top Layer w10: LED4.2@14702.03,3605 14732.5,3605 14953.38,3825.88 v1(14953.38,3945) ; v1(15203.38,4235) 15223.38,4255 U3.7@15242,4255
  Bottom Layer w10: v1(14953.38,3945) 14972.5,3945 15203.38,4175.88 v1(15203.38,4235)
DB9_12V: DB1.9 F2.1 | length 475.7
  Top Layer w10: DB1.9@17153.92,3864.09 17156.86,3867.03 17173.62,3867.03 17267.5,3960.91 17267.5,4079.07 17266.94,4079.63 17266.94,4100.35 17343.62,4177.03 F2.1@17417.5,4177.03
DB9_12V_F: D2.2 F2.2 | length 295.2
  Top Layer w10: D2.2@17182.5,4177.62 17225.12,4177.62 17370.47,4322.97 F2.2@17417.5,4322.97
DB_COM: DB1.8 H11.1 | length 2589.8
  Top Layer w10: v1(16437.61,4876.45) 16466.25,4847.81 v1(16466.25,4724.99)
  Inner2 w15: v1(16437.61,4876.45) 16437.61,5235.11 16478.25,5275.75 16616.75,5275.75 16673.11,5219.39 16801.29,5219.39 16811.89,5230 16811.89,5359.39 16822.5,5370 16872.5,5370 16952.5,5450 H11.1@16952.5,5530
  Bottom Layer w10: v1(16466.25,4724.99) 16466.25,4680.83 16622.99,4524.09 16743.41,4524.09 17262.99,4004.51 DB1.8@17262.98,3864.09
DB_DI0: DB1.6 H11.3 | length 2260.8
  Top Layer w10: v1(16731.1,4584.09) 16737.5,4590.5 16737.5,4675 16725,4687.5 16725,4717.5 16737.5,4730 16737.5,4962.69 v1(16731.1,4969.09)
  Inner2 w20: v1(16731.1,4969.09) 16821.59,4969.09 17082.5,5230 17082.5,5335 17152.5,5405 H11.3@17152.5,5530
  Bottom Layer w10: v1(16731.1,4584.09) 17271.1,4044.09 17321.1,4044.09 17371.1,3994.09 17371.1,3954.09 17461.1,3864.09 DB1.6@17481.09,3864.09
DB_DI1: DB1.7 H11.4 | length 2448.2
  Top Layer w10: v1(16755.83,5284.09) 16761.55,5278.37 v1(16761.55,4702.65) ; DB1.7@17372.03,3864.09 17372.04,4048.08 v1(17412.04,4088.08)
  Inner1 w20: v1(16755.83,5284.09) 16755.83,5333.33 16792.5,5370 17182.5,5370 17252.5,5440 H11.4@17252.5,5530
  Bottom Layer w10: v1(16761.55,4702.65) 16769.2,4695 16871.13,4695 16972.04,4594.09 16972.04,4530.46 17412.04,4090.46 v1(17412.04,4088.08)
DB_DO1: DB1.4 H10.4 | length 3891.4
  Inner1 w20: H10.4@16757.5,5530 16842.5,5445 v1(17012.5,5445)
  Inner2 w20: v1(17012.5,5445) 16987.5,5420 16987.5,5294.49 16675.26,4982.24 16675.26,4917.24 16697.5,4895 16932.5,4895 17087.5,5050 17667.5,5050 17757.5,4960 17912.5,4960 18007.5,4865 18007.5,4655 17982.5,4630 17982.5,4500 17872.5,4390 17742.5,4390 17562.5,4210 17297.5,4210 17212.5,4125 17212.5,3979.96 DB1.4@17208.44,3975.9
DB_SHELL: DB1.10 DB1.11 R31.1 | length 1404.3
  Top Layer w10: DB1.11@17809.63,3920 17809.63,4112.75 R31.1@17882.5,4185.63
  Top Layer w30: DB1.10@16825.38,3920 16975.38,3770 17659.62,3770 DB1.11@17809.63,3920
DC_JACK: DC1.1 F1.1 | length 169.9
  Top Layer w50: F1.1@16372.5,4107.03 16374.98,4104.55 16374.98,3978.11 DC1.1@16374.98,3938.14
DC_JACK_F: D1.2 F1.2 | length 555.8
  Top Layer w25: F1.2@16372.5,4252.97 16509.53,4252.97 16592.5,4170 16889.11,4170 D1.2@16892.5,4173.39
GND: C1.1 C2.1 C4.1 C5.1 C6.1 C7.2 C8.1 C9.1 C10.1 C11.1 C12.1 C13.2 C14.1 C15.1 C17.2 C18.2 C19.2 C20.1 CN1.1 CN2.1 D3.2 D7.2 DB1.5 DC1.2 H1.5 H2.4 H3.8 H8.2 H8.4 H11.2 LED1.1 LED3.1 Q2.2 Q3.2 R4.2 R5.2 R9.2 R13.2 R18.1 R20.2 R31.2 R32.2 R33.2 SCREW1.1 SCREW2.1 SCREW3.1 SCREW4.1 U1.4 U2.2 U3.1 U3.3 U3.9 U5.1 U5.2 U5.6 U6.2 U8.5 U8.10 U8.11 U9.2 USBC1.1 USBC1.2 USBC1.3 USBC1.4 USBC1.A1B12 USBC1.B1A12 USBC2.1 USBC2.2 USBC2.3 USBC2.4 USBC2.A1B12 USBC2.B1A12 | length 7052.8
  Top Layer w7.09: U8.5@16387.97,5077.13 16407.97,5077.13 16415.83,5085 16445.83,5085 ; U8.10@16447.03,5077.13 16445.83,5078.33 16445.83,5085 ; U8.11@16447.03,5092.87 16445.83,5091.68 16445.83,5085
  Top Layer w10: R18.1@15011.87,4820 R4.2@15011.87,4693.33 15011.87,4644.37 14971.87,4604.37 14971.87,4519.37 14976.24,4515 15011.87,4515 15011.87,4510.63 ; U3.3@15013,4205 15018,4210 15047.5,4210 ; LED1.1@15052.93,3635 15052.93,3629.57 15087.5,3595 15433.02,3595 15467.76,3629.74 15502.5,3595 15557.5,3595 15622.5,3660 15622.5,3687.87 15627.22,3692.59 ; v1(15127.5,4230) 15107.5,4210 15047.5,4210 ; R5.2@15193.13,4810 R20.2@15193.13,4685 15183.13,4685 15062.5,4564.37 15062.5,4535 15042.5,4515 15013.13,4515 15012.5,4514.37 15012.5,4511.26 15011.87,4510.63 ; USBC1.3@15707.23,3582.59 15707.22,3612.59 15627.22,3692.59 ; USBC1.4@15707.23,3747.15 15721.27,3747.15 USBC1.A1B12@15751.52,3777.41 ; R9.2@15771.87,4495 15775.97,4499.09 15775.97,4597.72 ; Q3.2@15775.97,4712.4 15735.97,4672.4 15735.97,4611.53 15749.78,4597.72 15775.97,4597.72 ; C7.2@15818.13,4140 15818.13,4125.63 15617.22,3924.72 15617.22,3702.59 15627.22,3692.59 ; Q2.2@15955.97,4338.37 15995.96,4378.37 15995.96,4587.72 15985.96,4597.72 ; USBC1.B1A12@16003.49,3777.41 16033.74,3747.15 USBC1.1@16047.77,3747.15 ; C15.1@16378.13,4630 16368.13,4640 16368.13,4920 16298.13,4920 16263.13,4885 16087.5,4885 15927.5,4725 15927.5,4700 15959.78,4667.72 15995.96,4667.72 16005.96,4657.72 16005.96,4617.72 15985.96,4597.72 ; C6.1@16378.13,4935 16438.13,4995 16462.5,4995 16532.5,5065 16532.5,5085 16525.43,5092.07 16464.57,5092.07 U8.10@16452.5,5080 ; U1.4@17204.9,4847.24 17210.21,4847.24 v1(17247.97,4885) ; USBC2.1@17952.23,5382.85 17966.26,5382.85 USBC2.B1A12@17996.51,5352.59 ; C19.2@18230.2,4580 C18.2@18230.2,4690 ; USBC2.A1B12@18248.48,5352.6 18278.73,5382.85 USBC2.4@18292.77,5382.85 ; 15011.87,4510.63 R13.2@15011.87,4440 15013,4438.86 U3.1@15013,4305 15022.5,4305 15057.5,4270 15057.5,4220 15047.5,4210 ; 15775.97,4597.72 15985.96,4597.72
  Top Layer w20: CN1.1@14326.87,4220 14322.5,4220 14307.5,4235 14307.5,4370 ; C9.1@14372.5,4514.37 14369.51,4511.38 14307.5,4511.38 ; U5.6@14507.5,4432.63 14504.85,4430 14504.85,4397.35 14477.5,4370 14307.5,4370 ; U5.2@14557.5,4637.37 14558.13,4637.99 14581.87,4637.99 ; U5.1@14607.5,4637.37 14582.5,4637.36 14581.87,4637.99 ; C2.1@16923.13,4765 16924.8,4763.33 C1.1@16924.8,4655 ; 14307.5,4370 14307.5,4511.38 ; 14307.5,4511.38 14307.5,4575 14352.5,4620 14415.08,4620 14422.5,4627.43 14422.5,4685 14432.5,4695 14557.5,4695 14581.87,4670.63 14581.87,4637.99
  Top Layer w25: C10.1@14362.5,4802.7 14362.5,4975.63 CN2.1@14402.5,5015.63 ; C8.1@15475.2,4185 C20.1@15475.2,4290 ; C17.2@17369.8,4695 17369.8,4780 C4.1@17342.5,4807.3 C5.1@17452.5,4807.3
  Top Layer w30: v1(15212.52,5070) C12.1@15268.13,5070 ; v1(16972.5,4175) 17036.18,4175 D3.2@17037.5,4173.68
  other v1: 15722.5,3905 15097.5,4185 15127.5,4185 15157.5,4185 15097.5,4230 15157.5,4230 15097.5,4275 15127.5,4275 15157.5,4275 17421.51,4460 17697.5,4490 17739.38,4490 17117.5,4530 17148.61,4530 17851.24,4576.26 15107.5,4670 18457.5,4880.56 18457.5,4910 18872.5,4910 16852.5,4930 16879.19,4930 18457.5,4940 18873.66,4942.7 18873.66,4973.54 17977.5,4990 15026,5035.02 14952.5,5095 18742.5,5340 18742.5,5405
ID_INV: Q2.1 Q3.3 R11.2 | length 1618
  Top Layer w10: v1(15696.28,4543.56) 15696.28,4674.06 Q3.3@15697.23,4675 ; v1(15911.28,4353.57) 15917.5,4347.35 15917.5,4277.35 15931.28,4263.57 Q2.1@15955.97,4263.57 ; v1(16066.28,4458.57) 16111.28,4413.57 16401.28,4413.57 16571.28,4583.56 16641.28,4583.56 16661.28,4603.56 16661.28,4663.56 16696.87,4699.16 R11.2@16696.87,4767.5
  Bottom Layer w20: v1(15696.28,4543.56) 15886.28,4353.57 v1(15911.28,4353.57) 15961.28,4353.57 v1(16066.28,4458.57)
LED_CHG_A: LED4.1 R15.2 | length 309.2
  Top Layer w10: R15.2@14621.87,3865 14572.97,3816.1 14572.97,3675 LED4.1@14642.97,3605
LED_DONE_A: LED2.2 R16.2 | length 251.3
  Top Layer w10: LED2.2@14701.99,3660.01 14717.5,3660 14791.87,3734.37 R16.2@14791.87,3865
LED_EXT_A: LED1.2 R12.2 | length 252.7
  Top Layer w10: LED1.2@15112.07,3635 15092.07,3655 15092.07,3830.2 R12.2@15126.87,3865
LED_ON_A: LED3.2 R29.2 | length 261
  Top Layer w10: LED3.2@15531.99,3635.01 15501.99,3665 15501.99,3820.12 R29.2@15546.87,3865
PROG: R13.1 U3.2 | length 234.9
  Top Layer w10: R13.1@14933.13,4440 14934.38,4438.75 14934.38,4305 14984.38,4255 U3.2@15013,4255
